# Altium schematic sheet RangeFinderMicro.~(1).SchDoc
size A
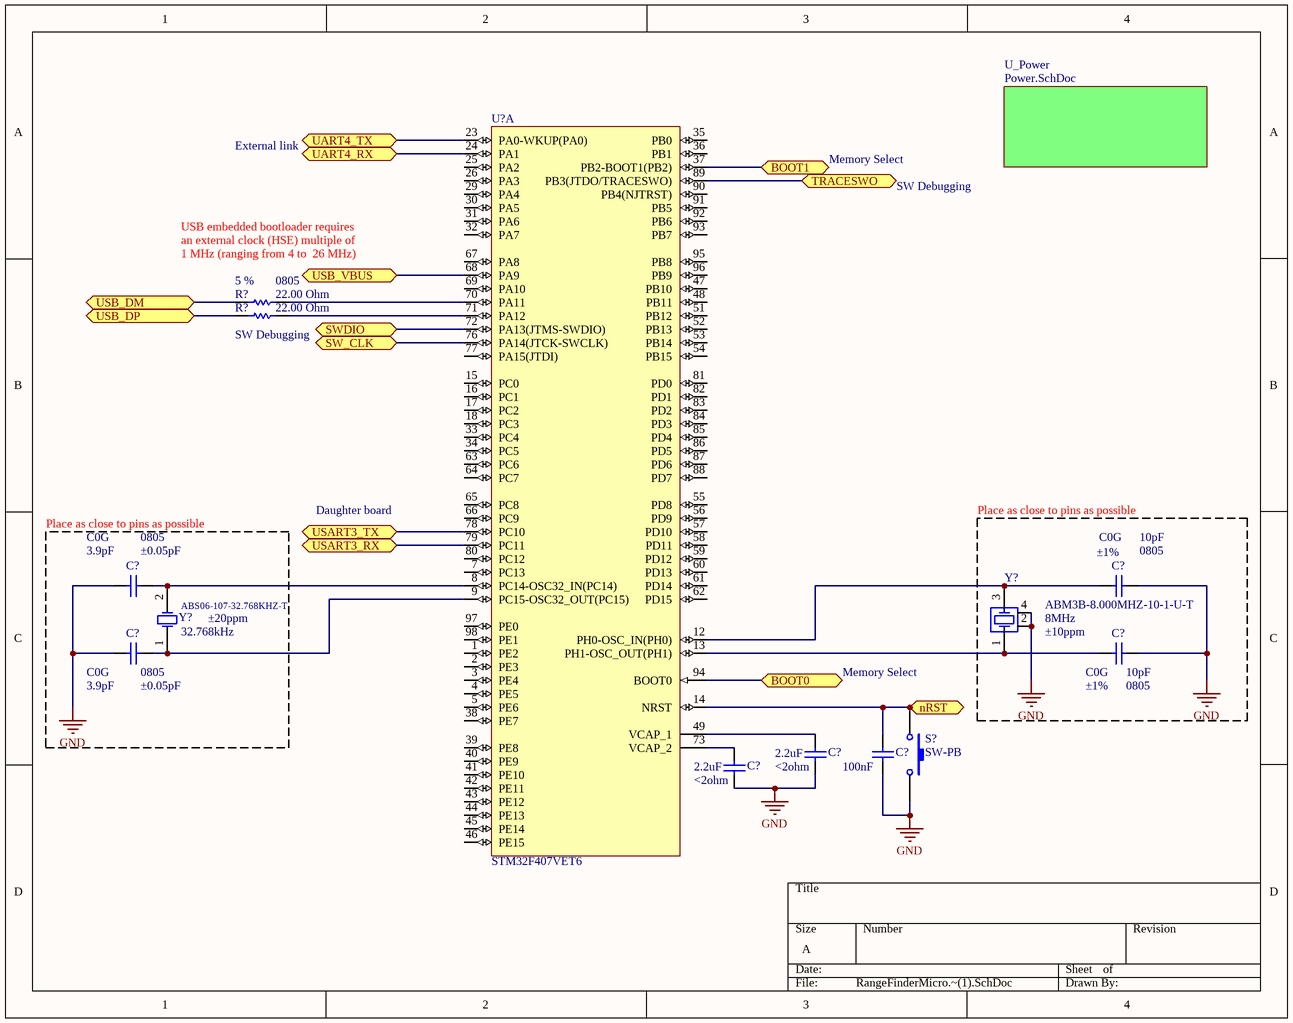
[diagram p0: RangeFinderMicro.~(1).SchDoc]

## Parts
(Parts that share a designator on the sheet are numbered #1, #2 ... from top to bottom, then left to right.)
C?#1  value 3.9pF  Case-EIA: 0805  Tolerance: ±0.05pF  Temperature Coefficient: C0G  [CAPC0805(2012)75_L]  (hidden comment: CAP 3.9pF 10V 0805(2012))
C?#2  value 10pF  Tolerance: ±1%  Case-EIA: 0805  Temperature Coefficient: C0G  [CAPC0805(2012)100_M]  (hidden comment: CAP 10pF 10V 0805(2012))
C?#3  value 3.9pF  Case-EIA: 0805  Tolerance: ±0.05pF  Temperature Coefficient: C0G  [CAPC0805(2012)75_L]  (hidden comment: CAP 3.9pF 10V 0805(2012))
C?#4  value 10pF  Tolerance: ±1%  Case-EIA: 0805  Temperature Coefficient: C0G  [CAPC0805(2012)100_M]  (hidden comment: CAP 10pF 10V 0805(2012))
C?#5  value 2.2uF  ESR: <2ohm  [CAPC0805(2012)145_M]  (hidden comment: CAP 1.5uF 6.3V 0805(2012))
C?#6  value 100nF  [CAPC0805(2012)145_M]  (hidden comment: CAP 100nF 0805(2012))
C?#7  value 2.2uF  ESR: <2ohm  [CAPC0805(2012)145_M]  (hidden comment: CAP 1.5uF 6.3V 0805(2012))
R?#1  value 22.00 Ohm  Tolerance: 5 %  Case-EIA: 0805  [RESC0805(2012)_M]  (hidden comment: 22R 5% 0805(2012))
R?#2  value 22.00 Ohm  [RESC0805(2012)_M]  (hidden comment: 22R 5% 0805(2012))
S?  SW-PB  [SPST-2]
U?  STM32F407VET6  [STM-LQFP100_M]  (part A of 2)
Y?#1  ABS06-107-32.768KHZ-T  Frequency: 32.768kHz  Frequency Tolerance: ±20ppm  [ABS06-107]
Y?#2  ABM3B-8.000MHZ-10-1-U-T  Frequency: 8MHz  Frequency Stability: ±10ppm  [ABM3B Series]

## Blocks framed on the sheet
Place as close to pins as possible: C?#1 C?#3 Y?#1
Place as close to pins as possible: C?#2 C?#4 Y?#2

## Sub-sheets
U_Power = Power.SchDoc: no entries

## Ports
BOOT0, BOOT1, nRST, SW_CLK, SWDIO, TRACESWO, UART4_RX, UART4_TX, USART3_RX, USART3_TX, USB_DM, USB_DP, USB_VBUS

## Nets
GND: C?#1.1 C?#2.2 C?#3.1 C?#4.2 C?#5.1 C?#6.1 C?#7.1 S?.2 Y?#2.2 Y?#2.4
BOOT0: U?.94(BOOT0) ; port BOOT0
BOOT1: U?.37(PB2-BOOT1(PB2)) ; port BOOT1
nRST: C?#6.2 S?.1 U?.14(NRST) ; port nRST
SW_CLK: U?.76(PA14(JTCK-SWCLK)) ; port SW_CLK
SWDIO: U?.72(PA13(JTMS-SWDIO)) ; port SWDIO
TRACESWO: U?.89(PB3(JTDO/TRACESWO)) ; port TRACESWO
UART4_RX: U?.24(PA1) ; port UART4_RX
UART4_TX: U?.23(PA0-WKUP(PA0)) ; port UART4_TX
USART3_RX: U?.79(PC11) ; port USART3_RX
USART3_TX: U?.78(PC10) ; port USART3_TX
USB_DM: R?#1.1 ; port USB_DM
USB_DP: R?#2.1 ; port USB_DP
USB_VBUS: U?.68(PA9) ; port USB_VBUS
NetC?#1_2: C?#1.2 U?.8(PC14-OSC32_IN(PC14)) Y?#1.2
NetC?#2_1: C?#2.1 U?.12(PH0-OSC_IN(PH0)) Y?#2.3
NetC?#3_2: C?#3.2 U?.9(PC15-OSC32_OUT(PC15)) Y?#1.1
NetC?#4_1: C?#4.1 U?.13(PH1-OSC_OUT(PH1)) Y?#2.1
NetC?#5_2: C?#5.2 U?.49(VCAP_1)
NetC?#7_2: C?#7.2 U?.73(VCAP_2)
NetR?#1_2: R?#1.2 U?.70(PA11)
NetR?#2_2: R?#2.2 U?.71(PA12)

Not connected (* = marked no-connect by the designer): U? 1(PE2) 2(PE3) 3(PE4) 4(PE5) 5(PE6) 7(PC13) 15(PC0) 16(PC1) 17(PC2) 18(PC3) 25(PA2) 26(PA3) 29(PA4) 30(PA5) 31(PA6) 32(PA7) 33(PC4) 34(PC5) 35(PB0) 36(PB1) 38(PE7) 39(PE8) 40(PE9) 41(PE10) 42(PE11) 43(PE12) 44(PE13) 45(PE14) 46(PE15) 47(PB10) 48(PB11) 51(PB12) 52(PB13) 53(PB14) 54(PB15) 55(PD8) 56(PD9) 57(PD10) 58(PD11) 59(PD12) 60(PD13) 61(PD14) 62(PD15) 63(PC6) 64(PC7) 65(PC8) 66(PC9) 67(PA8) 69(PA10) 77(PA15(JTDI)) 80(PC12) 81(PD0) 82(PD1) 83(PD2) 84(PD3) 85(PD4) 86(PD5) 87(PD6) 88(PD7) 90(PB4(NJTRST)) 91(PB5) 92(PB6) 93(PB7) 95(PB8) 96(PB9) 97(PE0) 98(PE1)

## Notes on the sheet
- External link
- Memory Select
- USB embedded bootloader requires
- SW Debugging
- an external clock (HSE) multiple of
- (near R?#1) 1 MHz (ranging from 4 to  26 MHz)
- (near R?#2) SW Debugging
- Daughter board

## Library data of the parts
C?#1 C?#3 = CMP-1036-00455-1: CAP 3.9pF 10V ±0.1pF 0805 (2012 Metric) Thickness 0.75mm SMD; Manufacturer Part Number: GRM1555C1H4R0WA01D; Case-Metric: 2012
C?#2 C?#4 = CMP-1036-00821-1: CAP 10pF 10V ±0.25pF 0805 (2012 Metric) Thickness 1mm SMD; Case-Metric: 2012
C?#5 C?#7 = CMP-1036-04784-1: CAP 1.5uF 6.3V ±20% 0805 (2012 Metric) Thickness 1.45mm SMD; Case-EIA: 0805; Case-Metric: 2012
C?#6 = CMP-1036-04784-1: CAP 1.5uF 6.3V ±20% 0805 (2012 Metric) Thickness 1.45mm SMD; Case-EIA: 0805; Case-Metric: 2012; ESR: <2ohm
R?#1 = CMP-1013-00034-1: 22R 0.125W 5% 0805 (2012 Metric)  SMD; Case-Metric: 2012
R?#2 = CMP-1013-00034-1: 22R 0.125W 5% 0805 (2012 Metric)  SMD; Case-Metric: 2012; Case-EIA: 0805
S? = SW-PB: Switch
U? = CMP-0243-00016-3: ARM Cortex-M4 32-bit MCU+FPU, 210 DMIPS, 512 kB Flash, 192 kB Internal RAM, 82 I/Os, 100-pin LQFP, -40 to 85 degC, Tray; Manufacturer: STMicroelectronics; Supply Voltage(Vcc) max (V): 3.6; Supply Voltage(Vcc) min (V): 1.8; I/Os (High Current): 82; FLASH Size (Prog) (kB): 512; Operating Frequency(F) (Processor speed) (MHz): 168; D/A Converter: 2x12-bit; Internal RAM Size (kB): 192
Y?#1 = ABS06-107: CRYSTAL 32.768 KHZ 4PF SMD; ESR (Equivalent Series Resistance): 60 kOhm; Operating Mode: Fundamental
Y?#2 = ABM3B Series: CRYSTAL 8MHZ 10PF SMD; ESR (Equivalent Series Resistance): 200 Ohm; Operating Mode: Fundamental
